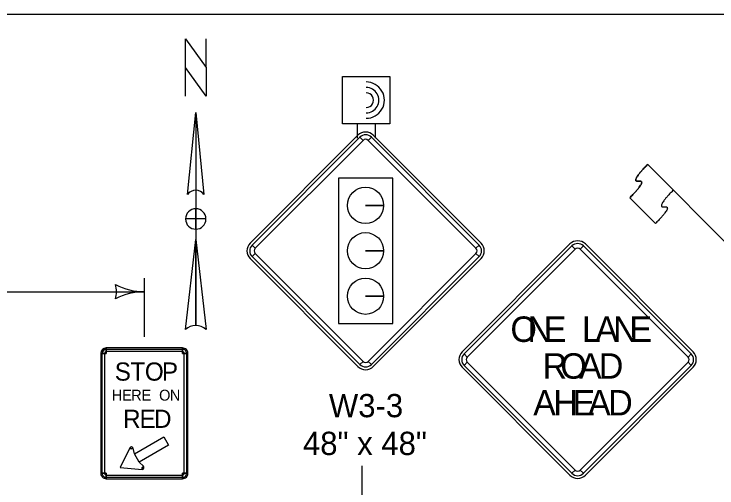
# Model space of a CAD drawing. Extents: x -2134934 to -2122394, y -2139046 to -2137036.
# Drawn here: x -2132604.2 to -2132120.1, y -2137362 to -2137035.9 of the extents above; entities that cross this region are included whole.
import ezdxf

# ---------------------------------------------------------------- set-up
doc = ezdxf.new("R2010")
doc.units = 0
for name, color, linetype in [('Barrier', 7, 'Continuous'), ('BridgeSuperStructureExisting', 7, 'Continuous'), ('Default', 7, 'Continuous'), ('dsnCellsScaleBlock', 7, 'Continuous'), ('DsnShtPlotShape', 7, 'Continuous'), ('TC_Barrier', 7, 'Continuous')]:
    doc.layers.add(name, color=color, linetype=linetype)

msp = doc.modelspace()

# ---------------------------------------------------------------- linework, layer by layer
at = {"layer": 'Barrier'}
for p, q in [((-2132367.37, -2137119.33), (-2132441.62, -2137193.57)), ((-2132366.05, -2137120.65), (-2132363.84, -2137122.86)), ((-2132360.3, -2137122.86), (-2132358.09, -2137120.65)), ((-2132282.52, -2137193.57), (-2132356.77, -2137119.33)), ((-2132110.46, -2137196.68), (-2132167.8, -2137139.38)), ((-2132167.8, -2137139.38), (-2132150.11, -2137157.06)), ((-2132162.49, -2137180.05), (-2132180.17, -2137162.37)), ((-2132349.66, -2137167.55), (-2132362.16, -2137167.55)), ((-2132362.16, -2137167.55), (-2132349.66, -2137167.55)), ((-2132221.34, -2137194.14), (-2132295.58, -2137268.39)), ((-2132136.48, -2137268.39), (-2132210.73, -2137194.14)), ((-2132438.08, -2137197.11), (-2132440.29, -2137194.9)), ((-2132349.66, -2137198.8), (-2132362.16, -2137198.8)), ((-2132362.16, -2137198.8), (-2132349.66, -2137198.8)), ((-2132283.85, -2137194.9), (-2132286.06, -2137197.11)), ((-2132220.01, -2137195.47), (-2132217.8, -2137197.68)), ((-2132214.27, -2137197.68), (-2132212.06, -2137195.47)), ((-2132440.29, -2137202.85), (-2132438.08, -2137200.64)), ((-2132286.06, -2137200.64), (-2132283.85, -2137202.85)), ((-2132441.62, -2137204.18), (-2132367.37, -2137278.43)), ((-2132356.77, -2137278.43), (-2132282.52, -2137204.18)), ((-2132349.66, -2137230.05), (-2132362.16, -2137230.05)), ((-2132362.16, -2137230.05), (-2132349.66, -2137230.05)), ((-2132540.7, -2137269.41), (-2132540.7, -2137265.66)), ((-2132540.7, -2137268.16), (-2132540.7, -2137266.6)), ((-2132488.2, -2137265.66), (-2132488.2, -2137269.41)), ((-2132488.2, -2137266.6), (-2132488.2, -2137268.16)), ((-2132544.45, -2137269.41), (-2132540.7, -2137269.41)), ((-2132543.51, -2137269.41), (-2132541.95, -2137269.41)), ((-2132488.2, -2137269.41), (-2132484.45, -2137269.41)), ((-2132486.95, -2137269.41), (-2132485.38, -2137269.41)), ((-2132292.05, -2137271.93), (-2132294.26, -2137269.72)), ((-2132137.81, -2137269.72), (-2132140.02, -2137271.93)), ((-2132363.84, -2137274.89), (-2132366.05, -2137277.1)), ((-2132358.09, -2137277.1), (-2132360.3, -2137274.89)), ((-2132294.26, -2137277.67), (-2132292.05, -2137275.46)), ((-2132140.02, -2137275.46), (-2132137.81, -2137277.67)), ((-2132295.58, -2137279), (-2132221.34, -2137353.24)), ((-2132210.73, -2137353.24), (-2132136.48, -2137279)), ((-2132524.59, -2137334.4), (-2132523.48, -2137334.98)), ((-2132523.48, -2137334.98), (-2132522.26, -2137334.7)), ((-2132515.98, -2137347.97), (-2132516.03, -2137349.22)), ((-2132515.13, -2137347.05), (-2132515.98, -2137347.97)), ((-2132540.7, -2137351.91), (-2132544.45, -2137351.91)), ((-2132541.95, -2137351.91), (-2132543.51, -2137351.91)), ((-2132540.7, -2137355.66), (-2132540.7, -2137351.91)), ((-2132540.7, -2137354.72), (-2132540.7, -2137353.16)), ((-2132484.45, -2137351.91), (-2132488.2, -2137351.91)), ((-2132488.2, -2137351.91), (-2132488.2, -2137355.66)), ((-2132488.2, -2137353.16), (-2132488.2, -2137354.72)), ((-2132485.38, -2137351.91), (-2132486.95, -2137351.91)), ((-2132217.8, -2137349.71), (-2132220.01, -2137351.92)), ((-2132212.06, -2137351.92), (-2132214.27, -2137349.71))]:
    msp.add_line(p, q, dxfattribs=at)
for points in [[(-2132366.05, -2137120.65), (-2132440.29, -2137194.9), (-2132438.08, -2137197.11), (-2132363.84, -2137122.86), (-2132366.05, -2137120.65)], [(-2132283.85, -2137194.9), (-2132358.09, -2137120.65), (-2132360.3, -2137122.86), (-2132286.06, -2137197.11), (-2132283.85, -2137194.9)], [(-2132343.34, -2137148.93), (-2132380.8, -2137148.93), (-2132380.8, -2137248.82), (-2132343.34, -2137248.82), (-2132343.34, -2137148.93)], [(-2132220.01, -2137195.47), (-2132294.26, -2137269.72), (-2132292.05, -2137271.93), (-2132217.8, -2137197.68), (-2132220.01, -2137195.47)], [(-2132137.81, -2137269.72), (-2132212.06, -2137195.47), (-2132214.27, -2137197.68), (-2132140.02, -2137271.93), (-2132137.81, -2137269.72)], [(-2132440.29, -2137202.85), (-2132366.05, -2137277.1), (-2132363.84, -2137274.89), (-2132438.08, -2137200.64), (-2132440.29, -2137202.85)], [(-2132358.09, -2137277.1), (-2132283.85, -2137202.85), (-2132286.06, -2137200.64), (-2132360.3, -2137274.89), (-2132358.09, -2137277.1)], [(-2132540.7, -2137355.66), (-2132488.2, -2137355.66), (-2132488.2, -2137351.91), (-2132484.45, -2137351.91), (-2132484.45, -2137269.41), (-2132488.2, -2137269.41), (-2132488.2, -2137265.66), (-2132540.7, -2137265.66), (-2132540.7, -2137269.41), (-2132544.45, -2137269.41), (-2132544.45, -2137351.91), (-2132540.7, -2137351.91), (-2132540.7, -2137355.66)], [(-2132488.2, -2137268.16), (-2132540.7, -2137268.16), (-2132540.7, -2137266.6), (-2132488.2, -2137266.6), (-2132488.2, -2137268.16)], [(-2132541.95, -2137269.41), (-2132541.95, -2137351.91), (-2132543.51, -2137351.91), (-2132543.51, -2137269.41), (-2132541.95, -2137269.41)], [(-2132486.95, -2137351.91), (-2132486.95, -2137269.41), (-2132485.38, -2137269.41), (-2132485.38, -2137351.91), (-2132486.95, -2137351.91)], [(-2132294.26, -2137277.67), (-2132220.01, -2137351.92), (-2132217.8, -2137349.71), (-2132292.05, -2137275.46), (-2132294.26, -2137277.67)], [(-2132212.06, -2137351.92), (-2132137.81, -2137277.67), (-2132140.02, -2137275.46), (-2132214.27, -2137349.71), (-2132212.06, -2137351.92)], [(-2132501.07, -2137326.91), (-2132497.79, -2137332.6), (-2132518.1, -2137344.32), (-2132521.38, -2137338.64), (-2132501.07, -2137326.91)], [(-2132531.1, -2137348.04), (-2132516.03, -2137349.22), (-2132515.98, -2137347.97), (-2132515.13, -2137347.05), (-2132518.1, -2137344.32), (-2132521.38, -2137338.64), (-2132522.26, -2137334.7), (-2132523.48, -2137334.98), (-2132524.59, -2137334.4), (-2132531.1, -2137348.04)], [(-2132540.7, -2137353.16), (-2132488.2, -2137353.16), (-2132488.2, -2137354.72), (-2132540.7, -2137354.72), (-2132540.7, -2137353.16)]]:
    msp.add_lwpolyline(points, close=True, dxfattribs=at)
for centre in [(-2132362.16, -2137167.55), (-2132362.16, -2137198.8), (-2132362.16, -2137230.05)]:
    msp.add_circle(centre, 12.5, dxfattribs=at)
for centre, radius, start, end in [((-2132362.07, -2137124.63), 7.5, 45, 134.9997), ((-2132362.07, -2137124.63), 5.62, 45, 134.9997), ((-2132362.07, -2137124.63), 2.5, 45, 134.9997), ((-2132436.32, -2137198.88), 7.5, 134.9997, 225), ((-2132287.83, -2137198.88), 7.5, 315.0002, 44.9998), ((-2132216.03, -2137199.45), 7.5, 45, 134.9997), ((-2132216.03, -2137199.45), 5.62, 45, 134.9997), ((-2132436.32, -2137198.88), 5.62, 134.9997, 225), ((-2132436.32, -2137198.88), 2.5, 134.9997, 225), ((-2132287.83, -2137198.88), 2.5, 315.0002, 44.9998), ((-2132287.83, -2137198.88), 5.62, 315.0002, 44.9998), ((-2132216.03, -2137199.45), 2.5, 45, 134.9997), ((-2132540.7, -2137269.41), 3.75, 90.0002, 179.9998), ((-2132540.7, -2137269.41), 2.81, 90.0002, 179.9998), ((-2132488.2, -2137269.41), 3.75, 0, 90.0002), ((-2132488.2, -2137269.41), 2.81, 0, 90.0002), ((-2132540.7, -2137269.41), 1.25, 90.0002, 179.9998), ((-2132488.2, -2137269.41), 1.25, 0, 90.0002), ((-2132290.28, -2137273.69), 7.5, 134.9997, 225), ((-2132290.28, -2137273.69), 5.62, 134.9997, 225), ((-2132141.79, -2137273.69), 5.62, 315.0002, 44.9998), ((-2132141.79, -2137273.69), 7.5, 315.0002, 44.9998), ((-2132362.07, -2137273.12), 2.5, 225, 315.0002), ((-2132290.28, -2137273.69), 2.5, 134.9997, 225), ((-2132141.79, -2137273.69), 2.5, 315.0002, 44.9998), ((-2132362.07, -2137273.12), 7.5, 225, 315.0002), ((-2132362.07, -2137273.12), 5.62, 225, 315.0002), ((-2132523.48, -2137334.98), 1.25, 12.6223, 152.2756), ((-2132515.98, -2137347.97), 1.25, 267.7243, 47.3776), ((-2132540.7, -2137351.91), 3.75, 179.9998, 270.0001), ((-2132540.7, -2137351.91), 2.81, 179.9998, 270.0001), ((-2132540.7, -2137351.91), 1.25, 179.9998, 270.0001), ((-2132488.2, -2137351.91), 3.75, 270.0001, 0.0003), ((-2132488.2, -2137351.91), 2.81, 270.0001, 0.0003), ((-2132488.2, -2137351.91), 1.25, 270.0001, 0.0003), ((-2132216.03, -2137347.94), 7.5, 225, 315.0002), ((-2132216.03, -2137347.94), 5.62, 225, 315.0002), ((-2132216.03, -2137347.94), 2.5, 225, 315.0002)]:
    msp.add_arc(centre, radius, start, end, dxfattribs=at)
for points in [[(-2132180.17, -2137162.37), (-2132167.8, -2137149.99), (-2132180.17, -2137151.77), (-2132167.8, -2137139.38)], [(-2132150.11, -2137157.06), (-2132162.49, -2137169.44), (-2132150.12, -2137167.67), (-2132162.49, -2137180.05)]]:
    msp.add_open_spline(points, degree=2, dxfattribs=at)
at = {"layer": 'BridgeSuperStructureExisting'}
for p, q in [((-2132367.91, -2137111.41), (-2132367.91, -2137121.41)), ((-2132355.41, -2137111.41), (-2132355.41, -2137121.41)), ((-2132514.45, -2137258.09), (-2132514.45, -2137217.69)), ((-2133178.02, -2137226.98), (-2132514.45, -2137226.98)), ((-2132364.45, -2137497.66), (-2132364.45, -2137346.75))]:
    msp.add_line(p, q, dxfattribs=at)
msp.add_lwpolyline([(-2132377.91, -2137111.41), (-2132377.91, -2137078.91), (-2132345.41, -2137078.91), (-2132345.41, -2137111.41)], close=True, dxfattribs=at)
for radius in [12.5, 12.5, 8.75, 5]:
    msp.add_arc((-2132361.65, -2137095.18), radius, 269.4041, 90.5445, dxfattribs=at)
at = {"layer": 'Default'}
msp.add_lwpolyline([(-2134934.44, -2137035.95), (-2131799.45, -2137035.95), (-2131799.45, -2139045.94), (-2134934.44, -2139045.94)], close=True, dxfattribs=at)
at = {"layer": 'dsnCellsScaleBlock'}
for p, q in [((-2132479.07, -2137103.67), (-2132473.43, -2137160.01)), ((-2132479.07, -2137103.67), (-2132479.07, -2137250.16)), ((-2132484.7, -2137160.01), (-2132484.7, -2137160.01)), ((-2132484.48, -2137159.49), (-2132483.43, -2137158.32)), ((-2132479.07, -2137183.96), (-2132479.07, -2137183.96)), ((-2132486.11, -2137252.98), (-2132479.07, -2137191))]:
    msp.add_line(p, q, dxfattribs=at)
msp.add_lwpolyline([(-2132472.02, -2137092.4), (-2132486.11, -2137072.68), (-2132486.11, -2137052.97), (-2132472.02, -2137072.68)], close=True, dxfattribs=at)
for points in [[(-2132486.11, -2137092.4), (-2132486.11, -2137052.97), (-2132472.02, -2137072.68), (-2132472.02, -2137052.97)], [(-2132484.7, -2137160.01), (-2132479.07, -2137103.67), (-2132479.07, -2137157.2)], [(-2132472.02, -2137176.92), (-2132479.07, -2137176.92), (-2132479.07, -2137169.87)], [(-2132479.07, -2137183.96), (-2132479.07, -2137176.92), (-2132486.11, -2137176.92)], [(-2132479.07, -2137250.16), (-2132479.07, -2137191), (-2132472.02, -2137252.98)]]:
    msp.add_lwpolyline(points, dxfattribs=at)
for centre, radius, start, end in [((-2132479.07, -2137164.24), 7.04, 90.0204, 143.1257), ((-2132479.07, -2137164.23), 7.04, 36.8481, 90.0218), ((-2132479.07, -2137176.92), 7.04, 90, 180), ((-2132479.07, -2137176.92), 7.04, 360, 90), ((-2132479.07, -2137176.92), 7.04, 180, 270), ((-2132479.07, -2137176.92), 7.04, 270, 360), ((-2132479.07, -2137260.36), 10.2, 89.9894, 133.619), ((-2132479.07, -2137260.37), 10.21, 46.4021, 90.0006)]:
    msp.add_arc(centre, radius, start, end, dxfattribs=at)
at = {"layer": 'DsnShtPlotShape'}
for centre, radius, start, end in [((-2132550.08, -2137226.98), 16.42, 342.2666, 17.7333), ((-2132514.45, -2137184.48), 42.5, 241.9275, 270), ((-2132514.45, -2137269.48), 42.5, 90, 118.0725)]:
    msp.add_arc(centre, radius, start, end, dxfattribs=at)
at = {"layer": 'TC_Barrier'}
msp.add_line((-2132180.17, -2137162.37), (-2132162.49, -2137180.05), dxfattribs=at)
for points in [[(-2132167.8, -2137139.38), (-2132180.17, -2137151.77), (-2132167.8, -2137149.99), (-2132180.17, -2137162.37)], [(-2132150.11, -2137157.06), (-2132162.49, -2137169.44), (-2132150.12, -2137167.67), (-2132162.49, -2137180.05)]]:
    msp.add_open_spline(points, degree=2, dxfattribs=at)

# ---------------------------------------------------------------- texts
at = {"layer": 'Barrier'}
for s, height, p in [('O', 17.5, (-2132262.32, -2137261.51)), ('N', 17.5, (-2132250.54, -2137261.51)), ('E', 17.5, (-2132239.32, -2137261.51)), ('L', 17.5, (-2132213.07, -2137261.51)), ('A', 17.5, (-2132203.87, -2137261.51)), ('N', 17.5, (-2132191.6, -2137261.51)), ('E', 17.5, (-2132180.37, -2137261.51)), ('R', 17.5, (-2132240.21, -2137286.82)), ('O', 17.5, (-2132227.92, -2137286.82)), ('A', 17.5, (-2132215.08, -2137286.82)), ('D', 17.5, (-2132201.43, -2137286.82)), ('S', 12.5, (-2132534.89, -2137288.16)), ('T', 12.5, (-2132524.13, -2137288.16)), ('O', 12.5, (-2132514.14, -2137288.16)), ('P', 12.5, (-2132502.4, -2137288.16)), ('H', 7.5, (-2132536.97, -2137301.91)), ('E', 7.5, (-2132529.82, -2137301.91)), ('R', 7.5, (-2132523.56, -2137301.91)), ('E', 7.5, (-2132516.41, -2137301.91)), ('O', 7.5, (-2132504.34, -2137301.91)), ('N', 7.5, (-2132496.96, -2137301.91)), ('A', 17.5, (-2132246.65, -2137312.13)), ('H', 17.5, (-2132232.78, -2137312.13)), ('E', 17.5, (-2132219.57, -2137312.13)), ('A', 17.5, (-2132208.85, -2137312.13)), ('D', 17.5, (-2132194.99, -2137312.13)), ('W3-3', 16, (-2132387.36, -2137313.34)), ('R', 12.5, (-2132529.13, -2137320.66)), ('E', 12.5, (-2132517.8, -2137320.66)), ('D', 12.5, (-2132507.84, -2137320.66)), ('48" x 48"', 16, (-2132405.24, -2137339.34))]:
    msp.add_text(s, height=height, dxfattribs=at).set_placement(p)

doc.saveas('drawing.dxf')
